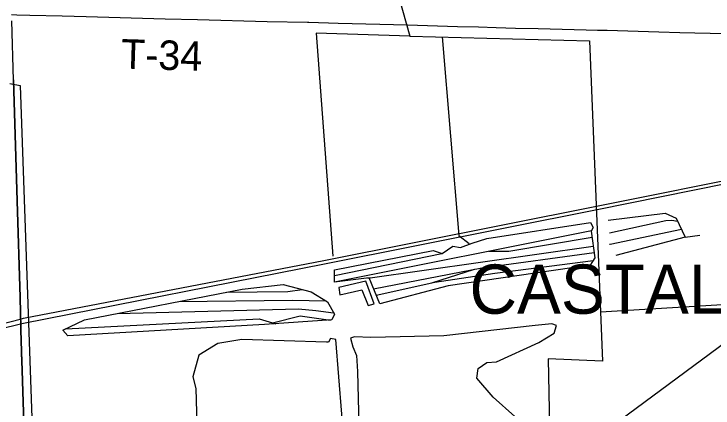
# Model space of a CAD drawing. Extents: x 0 to 34, y 0 to 22.
# Drawn here: x 6.04 to 6.712, y 14.353 to 14.733 of the extents above; entities that cross this region are included whole.
import ezdxf

# ---------------------------------------------------------------- set-up
doc = ezdxf.new("R2010")
doc.units = 0
for name, color, linetype in [('GM_X_Corporation', 7, 'Continuous'), ('GM_X_Corporation_Text', 7, 'Continuous'), ('GM_X_County_Road', 7, 'Continuous'), ('GM_X_Minor_Lake', 7, 'Continuous'), ('GM_X_Minor_River', 7, 'Continuous'), ('GM_X_Rail_Line', 7, 'Continuous'), ('GM_X_Township_Road', 7, 'Continuous'), ('GM_X_Township_Road_Text', 7, 'Continuous')]:
    doc.layers.add(name, color=color, linetype=linetype)

msp = doc.modelspace()

# ---------------------------------------------------------------- linework, layer by layer
at = {"layer": 'GM_X_Corporation'}
for points in [[(2.1, 14.1), (6.05687, 14.1), (6.05638, 14.11355), (6.05455, 14.1679), (6.05218, 14.24245), (6.05092, 14.27972), (6.04788, 14.37904), (6.04749, 14.3899), (6.04687, 14.40695), (6.04684, 14.41003), (6.04662, 14.41624), (6.04563, 14.45974), (6.04279, 14.55293), (6.04124, 14.60572), (6.0392, 14.6694)], [(3.23968, 14.1), (6.05687, 14.1), (6.05638, 14.11355), (6.05455, 14.1679), (6.05218, 14.24245), (6.05092, 14.27972), (6.04788, 14.37904), (6.04749, 14.3899), (6.04687, 14.40695), (6.04684, 14.41003), (6.04662, 14.41624), (6.04563, 14.45974), (6.04279, 14.55293), (6.04124, 14.60572), (6.0392, 14.6694)], [(6.0392, 14.6694), (6.04124, 14.60572), (6.04279, 14.55293), (6.04563, 14.45974), (6.04662, 14.41624), (6.04684, 14.41003), (6.04687, 14.40695), (6.04749, 14.3899), (6.04788, 14.37904), (6.05092, 14.27972), (6.05218, 14.24245), (6.05455, 14.1679), (6.05638, 14.11355), (6.05687, 14.1), (8.9, 14.1)], [(6.0392, 14.6694), (6.04124, 14.60572), (6.04279, 14.55293), (6.04563, 14.45974), (6.04662, 14.41624), (6.04684, 14.41003), (6.04687, 14.40695), (6.04749, 14.3899), (6.04788, 14.37904), (6.05092, 14.27972), (6.05218, 14.24245), (6.05455, 14.1679), (6.05638, 14.11355), (6.05687, 14.1), (8.65472, 14.1)]]:
    msp.add_lwpolyline(points, dxfattribs=at)
at = {"layer": 'GM_X_County_Road'}
msp.add_lwpolyline([(6.05697, 14.1), (6.05649, 14.11328), (6.05466, 14.16762), (6.05229, 14.24217), (6.05103, 14.27944), (6.04799, 14.37876), (6.0476, 14.38962), (6.04698, 14.40667), (6.04695, 14.40975), (6.04673, 14.41597), (6.04574, 14.45946), (6.0429, 14.55265), (6.04135, 14.60544), (6.03931, 14.66912), (6.03754, 14.72602)], dxfattribs=at)
at = {"layer": 'GM_X_Minor_Lake'}
for p, q in [((6.36723, 14.42195), (6.3636, 14.42064)), ((6.34227, 14.41662), (6.34037, 14.41663))]:
    msp.add_line(p, q, dxfattribs=at)
for points in [[(6.35326, 14.46237), (6.37441, 14.46716), (6.38058, 14.45208), (6.38629, 14.45375), (6.37828, 14.47549), (6.35221, 14.46933)], [(6.35221, 14.46933), (6.35326, 14.46237)], [(6.54246, 14.32666), (6.50089, 14.36387), (6.48524, 14.38206), (6.48645, 14.39137), (6.49467, 14.3972), (6.504, 14.39789), (6.54465, 14.41641), (6.55955, 14.42524), (6.5617, 14.43283), (6.55733, 14.43438), (6.54115, 14.4328), (6.4534, 14.42281), (6.38301, 14.42126), (6.36723, 14.42195)], [(6.34037, 14.41663), (6.25898, 14.41934), (6.23594, 14.41553), (6.2176, 14.40425), (6.21173, 14.38338), (6.2145, 14.37214), (6.21558, 14.33789)], [(6.35804, 14.31152), (6.34952, 14.41923), (6.34439, 14.42022), (6.34227, 14.41662)], [(6.3636, 14.42064), (6.36582, 14.41226), (6.36919, 14.40386), (6.37021, 14.38845), (6.37268, 14.28497)]]:
    msp.add_lwpolyline(points, dxfattribs=at)
at = {"layer": 'GM_X_Minor_River'}
for points in [[(6.40355, 14.77197), (6.42074, 14.71138), (6.59341, 14.70684), (6.60595, 14.39845), (6.55385, 14.40056), (6.55559, 14.30241), (6.53359, 14.28451), (6.52462, 14.28307)], [(6.42074, 14.71138), (6.33041, 14.71416), (6.3465, 14.49951)], [(6.45175, 14.71057), (6.46781, 14.51951), (6.47764, 14.51163)], [(6.03548, 14.66578), (6.04549, 14.66384), (6.06293, 14.17017)], [(6.61152, 14.5342), (6.66635, 14.54101), (6.67697, 14.53598), (6.68558, 14.51785), (6.61888, 14.50029)], [(6.34814, 14.48629), (6.44317, 14.50486), (6.4517, 14.50194), (6.45687, 14.50552), (6.46203, 14.50928), (6.46925, 14.50789), (6.48069, 14.51199), (6.4948, 14.51645), (6.59439, 14.53205), (6.59702, 14.52727), (6.59528, 14.52367), (6.59851, 14.49778), (6.59408, 14.49097), (6.45737, 14.4709), (6.39162, 14.45371), (6.38134, 14.47851), (6.34803, 14.47439), (6.34814, 14.48629)], [(6.61276, 14.52202), (6.66687, 14.53378), (6.67277, 14.53412), (6.67828, 14.53322)], [(6.61325, 14.51098), (6.68193, 14.52554)], [(6.34803, 14.47477), (6.59559, 14.52431)], [(6.68558, 14.51785), (6.69967, 14.51984)], [(6.49661, 14.50426), (6.51601, 14.50431), (6.59599, 14.51794)], [(6.38018, 14.47837), (6.59711, 14.509)], [(6.61288, 14.51093), (6.61325, 14.51098)], [(6.34809, 14.48086), (6.45153, 14.502)], [(6.38564, 14.46813), (6.48983, 14.48834), (6.59786, 14.50298)], [(6.38815, 14.46209), (6.44465, 14.47442), (6.50235, 14.48311), (6.59692, 14.49533)], [(6.44171, 14.47378), (6.48298, 14.48701)], [(6.08672, 14.42826), (6.10753, 14.43818), (6.25934, 14.46784), (6.29875, 14.47229), (6.3257, 14.46505), (6.34142, 14.45542), (6.34799, 14.44377), (6.34566, 14.43809), (6.28077, 14.43363), (6.09144, 14.42271), (6.08672, 14.42826)], [(6.24407, 14.46486), (6.30307, 14.46561), (6.31714, 14.46735)], [(6.19828, 14.45591), (6.30777, 14.45701), (6.33961, 14.45653)], [(6.60402, 14.446), (6.74274, 14.45428), (6.76785, 14.42879), (6.80794, 14.39844), (6.81695, 14.38163), (6.84913, 14.36066)], [(6.13905, 14.44434), (6.3136, 14.44898), (6.33014, 14.44733), (6.34725, 14.44509)], [(6.0894, 14.42954), (6.27549, 14.43919), (6.29156, 14.43437)], [(6.28855, 14.43527), (6.31507, 14.44193), (6.34436, 14.438)]]:
    msp.add_lwpolyline(points, dxfattribs=at)
at = {"layer": 'GM_X_Rail_Line'}
for points in [[(6.04866, 14.43974), (6.33792, 14.49548), (6.6004, 14.54763), (6.76038, 14.57982), (6.87836, 14.60396), (6.93973, 14.61737), (6.96714, 14.62422), (6.98978, 14.62988), (7.02315, 14.63763), (7.05235, 14.65372)], [(6.0488, 14.43506), (6.33852, 14.4922), (6.60099, 14.54435), (6.87866, 14.60068), (6.92409, 14.61131), (6.95441, 14.61781), (6.97131, 14.62124), (7.02524, 14.63495)], [(6.29906, 14.1), (6.44859, 14.21257), (6.77289, 14.45255), (6.9261, 14.56419), (7.02524, 14.63495)], [(4.70996, 14.1), (4.85491, 14.13841), (5.34537, 14.26094), (5.61522, 14.33076), (5.79332, 14.37664), (5.94586, 14.41322), (6.04675, 14.43934), (6.04866, 14.43974)], [(4.72932, 14.1), (4.85491, 14.13304), (5.34586, 14.25704), (5.61879, 14.32659), (5.80285, 14.37307), (5.94645, 14.40994), (6.04585, 14.43443), (6.0488, 14.43506)]]:
    msp.add_lwpolyline(points, dxfattribs=at)
at = {"layer": 'GM_X_Township_Road'}
for points in [[(6.03736, 14.73209), (6.04236, 14.73196), (6.0548, 14.73166), (6.08586, 14.73081), (6.10917, 14.73018), (6.18528, 14.72801), (6.21636, 14.72727), (6.28316, 14.72557), (6.32207, 14.72482)], [(6.32207, 14.72482), (6.32356, 14.72482), (6.35151, 14.72392), (6.41831, 14.72222), (6.46646, 14.72075), (6.48665, 14.72038), (6.50372, 14.71957), (6.52236, 14.71915), (6.54412, 14.71872), (6.59038, 14.71728), (6.60126, 14.71723), (6.61056, 14.71702), (6.66026, 14.71563), (6.68045, 14.71496), (6.72395, 14.7138), (6.75626, 14.71303), (6.76546, 14.71289), (6.7711, 14.71271)]]:
    msp.add_lwpolyline(points, dxfattribs=at)

# ---------------------------------------------------------------- texts
at = {"layer": 'GM_X_Corporation_Text'}
msp.add_text('CASTALIA', height=0.047348, rotation=0.00001, dxfattribs=at).set_placement((6.47805, 14.44412))
at = {"layer": 'GM_X_Township_Road_Text'}
msp.add_text('T-34', height=0.028409, rotation=358.23498, dxfattribs=at).set_placement((6.14236, 14.68021))

doc.saveas('drawing.dxf')
